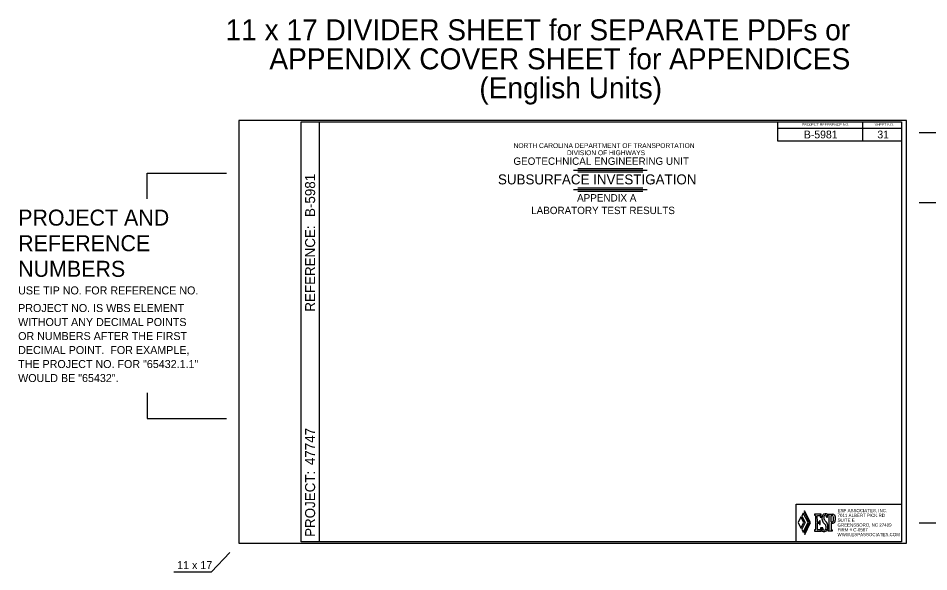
# Model space of a CAD drawing. Extents: x 265553 to 275568, y 168312 to 173522.
# Drawn here: x 266163 to 268437, y 168451 to 169834 of the extents above; entities that cross this region are included whole.
import ezdxf

# ---------------------------------------------------------------- set-up
doc = ezdxf.new("R2010")
doc.units = 0
for name, color, linetype in [('Default', 7, 'Continuous'), ('Geotech Sheets and Borders Cell', 7, 'Continuous'), ('Prop Strc Sect_ Border - minor', 7, 'Continuous'), ('Scratch_Level_0', 7, 'Continuous'), ('Scratch_Level_2', 7, 'Continuous'), ('Scratch_Level_4', 7, 'Continuous'), ('Scratch_Level_6', 7, 'Continuous'), ('Sheet Plot Border Inside CELL', 7, 'Continuous')]:
    doc.layers.add(name, color=color, linetype=linetype)

msp = doc.modelspace()

# ---------------------------------------------------------------- linework, layer by layer
at = {"layer": 'Default'}
for p, q in [((268168.5, 168594.3), (268151.9, 168594.3)), ((268151.9, 168594.3), (268151.9, 168591.7)), ((268151.9, 168591.7), (268153.4, 168591.5)), ((268159, 168575), (268158.9, 168591.2)), ((268159.3, 168591.5), (268164.9, 168591.5)), ((268168.5, 168586.7), (268168.5, 168594.3)), ((268184.2, 168594.3), (268181.9, 168595.2)), ((268184.2, 168586.8), (268184.2, 168594.3)), ((268186.4, 168594.3), (268194.4, 168594.3)), ((268186.4, 168591.8), (268186.4, 168594.3)), ((268187.9, 168591.5), (268186.4, 168591.8)), ((268193.3, 168591.6), (268195.5, 168591.6)), ((268193.3, 168574.8), (268193.3, 168591.6)), ((268194.4, 168594.3), (268197.5, 168594.5)), ((268154.4, 168590.3), (268154.4, 168561.2)), ((268159, 168560.8), (268159, 168572.1)), ((268163.4, 168574.8), (268159.2, 168574.7)), ((268159.2, 168572.3), (268163.4, 168572.3)), ((268166.2, 168578), (268164.6, 168578)), ((268164.6, 168578), (268164.6, 168575.9)), ((268164.6, 168571.2), (268164.6, 168569)), ((268164.6, 168569), (268166.2, 168569)), ((268166.1, 168590.4), (268166.2, 168586.7)), ((268166.2, 168586.7), (268168.5, 168586.7)), ((268166.2, 168569), (268166.2, 168578)), ((268181.8, 168588.3), (268181.8, 168586.8)), ((268181.8, 168586.8), (268184.2, 168586.8)), ((268188.9, 168562.3), (268188.8, 168590.3)), ((268195.3, 168574.8), (268193.3, 168574.8)), ((268193.3, 168571.9), (268193.3, 168559.4)), ((268196.6, 168575), (268195.3, 168574.8)), ((268198.6, 168588.8), (268199.1, 168587)), ((268153.1, 168555.2), (268151.9, 168555.2)), ((268151.9, 168555.2), (268151.9, 168552.5)), ((268151.9, 168552.5), (268169.2, 168552.5)), ((268154.4, 168561.2), (268154.3, 168556.3)), ((268159.2, 168556.5), (268159, 168560.8)), ((268165.6, 168555.4), (268160.3, 168555.4)), ((268166.8, 168560.5), (268166.7, 168556.6)), ((268169.2, 168560.5), (268166.8, 168560.5)), ((268169.2, 168552.5), (268169.2, 168560.5)), ((268172.9, 168560.5), (268170.6, 168560.5)), ((268170.6, 168560.5), (268170.6, 168552.5)), ((268172.9, 168558.5), (268172.9, 168560.5)), ((268186.4, 168552.5), (268186.4, 168555.3)), ((268186.4, 168555.3), (268187.5, 168555.3)), ((268196.2, 168552.5), (268186.4, 168552.5)), ((268188.7, 168556.4), (268188.9, 168562.3)), ((268193.3, 168559.4), (268193.5, 168556.4)), ((268194.6, 168555.3), (268196.2, 168555.3)), ((268196.2, 168555.3), (268196.2, 168552.5))]:
    msp.add_line(p, q, dxfattribs=at)
for points in [[(268120.1, 168590), (268128.3, 168573.6), (268120.2, 168557), (268123.9, 168549.5), (268135.7, 168573.6), (268123.8, 168597.5), (268120.1, 168590)], [(268125.7, 168600.1), (268138.9, 168573.6), (268125.8, 168546.9), (268127.4, 168543.7), (268142.1, 168573.6), (268127.3, 168603.3), (268125.7, 168600.1)], [(268118, 168587.6), (268111.1, 168573.4), (268118, 168559.4), (268125, 168573.6), (268118, 168587.6)]]:
    msp.add_lwpolyline(points, dxfattribs=at)
for centre, radius, start, end in [((268153.2, 168590.3), 1.15, 0.0607, 81.368), ((268159.3, 168591.2), 0.31, 90.0607, 180.0607), ((268164.9, 168590.4), 1.15, 1.9943, 90.0607), ((268183.4, 168585.1), 12.8, 132.277, 178.7717), ((268179.3, 168583.5), 11.9, 77.4945, 112.607), ((268180.8, 168587.8), 5.7, 127.7022, 172.2101), ((268178.5, 168590), 2.59, 40.3385, 117.3766), ((268176.2, 168588.1), 5.53, 2.0028, 40.3385), ((268187.6, 168590.3), 1.18, 0.0607, 79.8192), ((268194.8, 168587.7), 3.99, 16.8704, 79.0876), ((268197.8, 168589.1), 5.43, 34.4894, 93.4478), ((268190.5, 168585.4), 13.6, 7.0821, 29.7759), ((268159.2, 168575), 0.22, 180.0607, 270.0607), ((268159.2, 168572.1), 0.22, 90.0607, 180.0607), ((268163.4, 168575.9), 1.15, 270.0607, 0.0607), ((268163.4, 168571.2), 1.15, 0.0607, 90.0607), ((268186.5, 168583.8), 16, 174.413, 211.2268), ((268193.4, 168587.4), 23.8, 210.18, 228.2816), ((268192.1, 168585.6), 17.2, 170.1104, 185.809), ((268184.5, 168586.5), 9.9, 195.0144, 224.5602), ((268731.3, 169090.3), 753.4, 222.6822, 223.0182), ((268171.8, 168562.7), 9.09, 3.0107, 50.83), ((268163.5, 168560.4), 23.2, 30.8042, 43.0163), ((268171.9, 168565.3), 13.5, 9.1866, 31.2488), ((268190.4, 168644.7), 72.8, 272.3182, 275.4374), ((268194.6, 168579.3), 4.69, 295.2092, 355.4805), ((268196.4, 168580.9), 8.8, 275.4374, 295.5502), ((268171.2, 168582.5), 28.3, 352.8067, 9.1634), ((268197.9, 168577.9), 5.42, 295.5502, 327.7187), ((268193.3, 168580.5), 10.7, 328.9362, 353.7339), ((268168.3, 168583.4), 35.9, 353.4945, 5.8911), ((268153.1, 168556.4), 1.15, 270.0607, 358.0948), ((268160.3, 168556.6), 1.15, 183.0592, 270.0607), ((268165.6, 168556.6), 1.15, 270.0607, 358.1271), ((268175.8, 168565.6), 14.1, 248.6025, 262.4993), ((268177, 168558.4), 4.1, 179.1725, 260.7014), ((268176.5, 168571.1), 19.6, 262.6129, 273.4517), ((268176.8, 168557.9), 3.52, 262.5493, 350.6871), ((268177.1, 168558.6), 7.12, 274.5621, 307.9936), ((268165.3, 168561.8), 15.7, 343.132, 4.7325), ((268174.4, 168560.7), 10.5, 312.5245, 339.8341), ((268168.7, 168563.3), 16.7, 338.2327, 357.7166), ((268161.9, 168564.1), 23.6, 356.494, 8.3188), ((268187.5, 168556.4), 1.15, 270.0607, 358.0948), ((268194.6, 168556.4), 1.15, 183.0592, 270.0607)]:
    msp.add_arc(centre, radius, start, end, dxfattribs=at)
at = {"layer": 'Geotech Sheets and Borders Cell'}
for p, q in [((266914.3, 169575.4), (266914.3, 168525.3)), ((268271.8, 169575.3), (268271.8, 169526.6)), ((268060.5, 169559.1), (268369.3, 169559.1)), ((267560.9, 169458.9), (267722.7, 169458.9)), ((267549.6, 169454.5), (267734, 169454.5)), ((267560.9, 169450.2), (267722.7, 169450.2)), ((267560.9, 169410.6), (267722.7, 169410.6)), ((267549.6, 169406.3), (267734, 169406.3)), ((267560.9, 169402), (267722.7, 169402))]:
    msp.add_line(p, q, dxfattribs=at)
for points in [[(266869.3, 169575.3), (268369.3, 169575.3), (268369.3, 168525.3), (266869.3, 168525.3)], [(268060.5, 169575.3), (268369.3, 169575.3), (268369.3, 169526.6), (268060.5, 169526.6)]]:
    msp.add_lwpolyline(points, close=True, dxfattribs=at)
at = {"layer": 'Scratch_Level_0'}
for p, q in [((268381.8, 169578.1), (268381.8, 169578.1)), ((266714.1, 168522.5), (266714.1, 168522.5))]:
    msp.add_line(p, q, dxfattribs=at)
msp.add_lwpolyline([(266551.5, 168450.6), (266645.3, 168450.6), (266691.2, 168498.5)], dxfattribs=at)
at = {"layer": 'Scratch_Level_4'}
for points in [[(268611.2, 169611.9), (268611.2, 169547.8), (268413.1, 169547.8)], [(266484.7, 169382.5), (266484.7, 169446.7), (266682.8, 169446.7)], [(268611.2, 169308.3), (268611.2, 169372.4), (268413.1, 169372.4)], [(266484.7, 168898), (266484.7, 168833.8), (266682.8, 168833.8)], [(268611.2, 168522.5), (268611.2, 168572.4), (268413.1, 168572.4)]]:
    msp.add_lwpolyline(points, dxfattribs=at)
at = {"layer": 'Scratch_Level_6'}
msp.add_lwpolyline([(268106.3, 168619.6), (268369.3, 168619.6), (268369.3, 168525.3), (268106.3, 168525.3)], close=True, dxfattribs=at)
at = {"layer": 'Sheet Plot Border Inside CELL'}
msp.add_lwpolyline([(266714.1, 168522.5), (268381.8, 168522.5), (268381.8, 169578.1), (266714.1, 169578.1)], close=True, dxfattribs=at)

# ---------------------------------------------------------------- texts
at = {"layer": 'Geotech Sheets and Borders Cell'}
for s, height, p in [('PROJECT REFERENCE NO.', 6.5, (268120.5, 169565.2)), ('SHEET NO.', 6.5, (268301.9, 169565.2)), ('B-5981', 19.5, (268125.4, 169533.8)), ('31', 19.5, (268309, 169533.8)), ('NORTH CAROLINA DEPARTMENT OF TRANSPORTATION', 12, (267400.2, 169509.7)), ('DIVISION OF HIGHWAYS', 12, (267533.5, 169491.9)), ('GEOTECHNICAL ENGINEERING UNIT', 18.45, (267399.7, 169467.7)), ('SUBSURFACE INVESTIGATION', 25, (267361.1, 169418.8)), ('APPENDIX A', 18.45, (267558.8, 169376)), ('LABORATORY TEST RESULTS', 18.45, (267444, 169344.6))]:
    msp.add_text(s, height=height, dxfattribs=at).set_placement(p)
for s, p in [('B-5981', (266904.3, 169337.4)), ('REFERENCE:', (266904.3, 169100.8)), ('47747', (266904.3, 168717.2)), ('PROJECT:', (266904.3, 168537.8))]:
    msp.add_text(s, height=25, rotation=90, dxfattribs=at).set_placement(p)
at = {"layer": 'Prop Strc Sect_ Border - minor'}
for s, p in [('7011 ALBERT PICK RD', (268209.4, 168587.6)), ('ESP ASSOCIATES, INC.', (268209.4, 168599.6)), ('SUITE E', (268209.4, 168575.6)), ('GREENSBORO, NC 27409 ', (268209.4, 168563.6)), ('WWW.ESPASSOCIATES.COM', (268209.4, 168539.6)), ('FIRM # C-0587', (268209.4, 168551.6))]:
    msp.add_text(s, height=8, dxfattribs=at).set_placement(p)
at = {"layer": 'Scratch_Level_0'}
msp.add_text('11 x 17', height=20, dxfattribs=at).set_placement((266559.6, 168457.3))
at = {"layer": 'Scratch_Level_2'}
for s, p in [('11 x 17 DIVIDER SHEET for SEPARATE PDFs or', (266680.5, 169778.9)), ('APPENDIX COVER SHEET for APPENDICES', (266790, 169706.4)), ('(English Units)', (267314.6, 169633.9))]:
    msp.add_text(s, height=52.5, dxfattribs=at).set_placement(p)
at = {"layer": 'Scratch_Level_4'}
for s, height, p in [('PROJECT AND', 40, (266162.4, 169315.8)), ('REFERENCE', 40, (266162.4, 169251.8)), ('NUMBERS', 40, (266162.4, 169187.8)), ('USE TIP NO. FOR REFERENCE NO.', 20, (266162.4, 169143.8)), ('PROJECT NO. IS WBS ELEMENT', 20, (266162.4, 169099.8)), ('WITHOUT ANY DECIMAL POINTS', 20, (266162.4, 169064.8)), ('OR NUMBERS AFTER THE FIRST', 20, (266162.4, 169029.8)), ('DECIMAL POINT.  FOR EXAMPLE,', 20, (266162.4, 168994.8)), ('THE PROJECT NO. FOR "65432.1.1"', 20, (266162.4, 168959.8)), ('WOULD BE "65432".', 20, (266162.4, 168924.8))]:
    msp.add_text(s, height=height, dxfattribs=at).set_placement(p)

doc.saveas('drawing.dxf')
